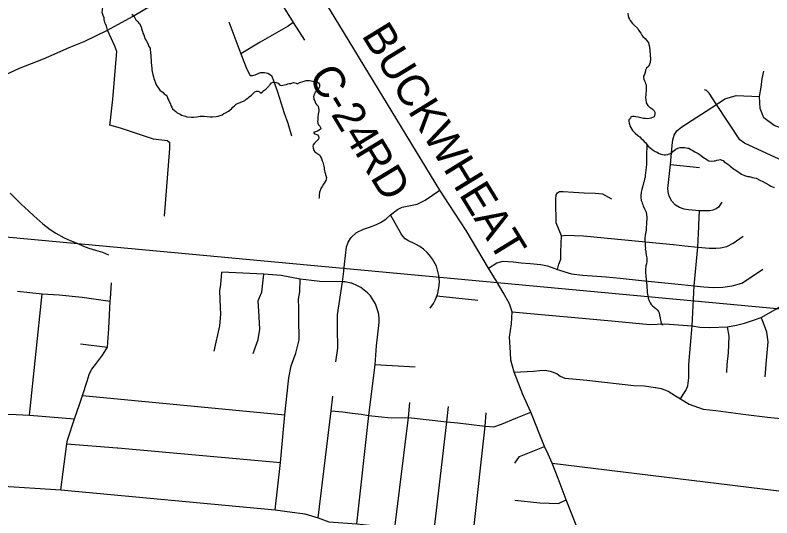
# Model space of a CAD drawing. Extents: x 0 to 34, y 0 to 22.
# Drawn here: x 7.879 to 8.564, y 19.556 to 20.011 of the extents above; entities that cross this region are included whole.
import ezdxf

# ---------------------------------------------------------------- set-up
doc = ezdxf.new("R2010")
doc.units = 0
for name, color, linetype in [('GM_X_County_Road', 7, 'Continuous'), ('GM_X_County_Road_Text', 7, 'Continuous'), ('GM_X_Minor_River', 7, 'Continuous'), ('GM_X_Rail_Line', 7, 'Continuous'), ('GM_X_State_Route', 7, 'Continuous'), ('GM_X_Township_Road', 7, 'Continuous')]:
    doc.layers.add(name, color=color, linetype=linetype)

msp = doc.modelspace()

# ---------------------------------------------------------------- linework, layer by layer
at = {"layer": 'GM_X_County_Road'}
msp.add_lwpolyline([(8.39269, 19.53489), (8.37799, 19.57233), (8.37085, 19.59153), (8.36519, 19.60541), (8.36182, 19.61363), (8.35845, 19.62064), (8.34603, 19.65165), (8.33882, 19.66764), (8.33096, 19.68798), (8.32794, 19.69886), (8.32754, 19.70571), (8.3267, 19.71954), (8.32834, 19.73169), (8.32893, 19.7424), (8.32665, 19.74986), (8.32103, 19.7599), (8.3148, 19.77035), (8.30767, 19.78207), (8.28725, 19.81622), (8.27202, 19.8398), (8.26366, 19.85264), (8.11273, 20.10048)], dxfattribs=at)
at = {"layer": 'GM_X_Minor_River'}
for points in [[(7.98432, 20.01186), (7.98618, 20.01049), (7.98727, 20.00856), (7.98818, 20.00702), (7.98929, 20.00567), (7.99151, 20.00333), (7.99277, 20.00065), (7.99311, 19.99893), (7.99418, 19.99625), (7.99452, 19.99472), (7.99524, 19.99319), (7.99595, 19.99108), (7.9963, 19.98993), (7.99775, 19.98743), (7.99884, 19.98532), (7.99972, 19.98264), (8.00102, 19.98128), (8.00116, 19.97957), (8.00149, 19.97766), (8.00179, 19.97424), (8.00174, 19.97254), (8.00189, 19.97083), (8.00201, 19.96798), (8.00215, 19.96589), (8.00245, 19.96266), (8.00261, 19.96152), (8.00295, 19.96018), (8.00345, 19.95732), (8.00397, 19.95541), (8.0045, 19.95369), (8.00484, 19.95236), (8.00592, 19.94986), (8.00644, 19.94795), (8.00865, 19.94505), (8.00974, 19.94313), (8.01291, 19.94096), (8.01383, 19.9398), (8.01551, 19.93862), (8.01643, 19.93745), (8.01714, 19.93535), (8.01786, 19.93381), (8.01949, 19.93055), (8.01983, 19.92921), (8.02074, 19.92767), (8.02128, 19.92633), (8.02426, 19.92398), (8.02537, 19.92281), (8.02837, 19.9214), (8.02949, 19.92062), (8.03307, 19.91958), (8.03439, 19.91916), (8.03837, 19.91887), (8.04027, 19.91863), (8.04331, 19.91893), (8.04637, 19.91961), (8.04751, 19.91977), (8.04998, 19.9197), (8.05281, 19.91925), (8.05528, 19.919), (8.05755, 19.91894), (8.06098, 19.91923), (8.0627, 19.91975), (8.06461, 19.92027), (8.06615, 19.92099), (8.06789, 19.92208), (8.06923, 19.92261), (8.07212, 19.92424), (8.07465, 19.92645), (8.07601, 19.92793), (8.07737, 19.92904), (8.07893, 19.93051), (8.08008, 19.93124), (8.08162, 19.93177), (8.08565, 19.93337), (8.0868, 19.93391), (8.08816, 19.9352), (8.0897, 19.93611), (8.09087, 19.93722), (8.09281, 19.93868), (8.09456, 19.94053), (8.09593, 19.94182), (8.09746, 19.94235), (8.09898, 19.94231)], [(8.43387, 20.01302), (8.43418, 20.01036), (8.43453, 20.00902), (8.43544, 20.00748), (8.43597, 20.00614), (8.43819, 20.00362), (8.43929, 20.00226)], [(8.43929, 20.00226), (8.44282, 19.99895), (8.44354, 19.9976), (8.44575, 19.9947), (8.44665, 19.99297), (8.44757, 19.99181), (8.44943, 19.99005), (8.45072, 19.9885), (8.45183, 19.98734), (8.45275, 19.98598), (8.4529, 19.98465), (8.45325, 19.98351), (8.45373, 19.9797), (8.45388, 19.97837), (8.45401, 19.9759), (8.45397, 19.97438), (8.45428, 19.97172), (8.4542, 19.96831), (8.45359, 19.96681), (8.45278, 19.96493), (8.45065, 19.96309), (8.44984, 19.96141), (8.4496, 19.95933), (8.44898, 19.95745), (8.44819, 19.95595), (8.44796, 19.95463), (8.44831, 19.95329), (8.44884, 19.95157), (8.44957, 19.95042), (8.44992, 19.94927), (8.45046, 19.94812), (8.45059, 19.94584), (8.4505, 19.94243), (8.45027, 19.94054), (8.45004, 19.93922), (8.44997, 19.93619), (8.45012, 19.93466), (8.45043, 19.93181), (8.45207, 19.92931), (8.45355, 19.92775), (8.45468, 19.92715), (8.45636, 19.92597), (8.45765, 19.92442), (8.45819, 19.92327), (8.45834, 19.92175), (8.4577, 19.91911), (8.45482, 19.91786), (8.45348, 19.91751), (8.45196, 19.91736), (8.44987, 19.91742), (8.44798, 19.91765), (8.44571, 19.91809), (8.44326, 19.91873), (8.44118, 19.91897), (8.43948, 19.91939), (8.43796, 19.91943), (8.43662, 19.91909), (8.43621, 19.91796), (8.43484, 19.91629), (8.43481, 19.91515), (8.43515, 19.91344), (8.43602, 19.91019), (8.43801, 19.90654), (8.44042, 19.9042), (8.44284, 19.90224), (8.44471, 19.90086), (8.446, 19.8995), (8.44749, 19.89814), (8.44859, 19.89678), (8.45008, 19.89541), (8.45099, 19.89406), (8.45228, 19.89251), (8.45377, 19.89115), (8.456, 19.88938), (8.45862, 19.8878), (8.46031, 19.88699), (8.46162, 19.8862), (8.46388, 19.88538), (8.4667, 19.88455), (8.46803, 19.88452), (8.46975, 19.88485), (8.47358, 19.88627), (8.47476, 19.88757), (8.47728, 19.88977), (8.4792, 19.89067), (8.48131, 19.89119), (8.48397, 19.89131), (8.4853, 19.89127), (8.48681, 19.89104), (8.48813, 19.89082), (8.48927, 19.8906), (8.49039, 19.88981), (8.49207, 19.88882), (8.4945, 19.88724), (8.4975, 19.88583), (8.49937, 19.88465), (8.50124, 19.88327), (8.50328, 19.88151), (8.50459, 19.88091), (8.5059, 19.88011), (8.5074, 19.87932)], [(8.09898, 19.94231), (8.1001, 19.94172), (8.10121, 19.94055), (8.10276, 19.94184), (8.10411, 19.94275), (8.10586, 19.94422), (8.10742, 19.9457), (8.11015, 19.94866), (8.11113, 19.94977), (8.11247, 19.95031), (8.11532, 19.95023), (8.11701, 19.94962), (8.1183, 19.94807), (8.12019, 19.94745), (8.12286, 19.94814), (8.12458, 19.94847), (8.12592, 19.94882), (8.12707, 19.94916), (8.1284, 19.94932), (8.12955, 19.94967), (8.13088, 19.95001), (8.13202, 19.94998), (8.13334, 19.94957), (8.13466, 19.94897), (8.13678, 19.95024), (8.13983, 19.95092), (8.14252, 19.95199), (8.14556, 19.95191), (8.14688, 19.95168), (8.1482, 19.95127), (8.15028, 19.95102), (8.15255, 19.95059), (8.15367, 19.94999), (8.1544, 19.94864), (8.15437, 19.9475), (8.15453, 19.94636), (8.15393, 19.94505), (8.15333, 19.94393), (8.15196, 19.94226), (8.1506, 19.94116), (8.14981, 19.93985), (8.14921, 19.93854), (8.14917, 19.93702), (8.14933, 19.93588), (8.14949, 19.93474), (8.15022, 19.93358), (8.15092, 19.93129), (8.15165, 19.93013), (8.15313, 19.92857), (8.15366, 19.92704), (8.15382, 19.9259), (8.15379, 19.92458), (8.15334, 19.92156), (8.15289, 19.91891), (8.15286, 19.91759), (8.15282, 19.91626), (8.15279, 19.91493), (8.15294, 19.91341), (8.15366, 19.91188), (8.15477, 19.91052), (8.15531, 19.90937), (8.15566, 19.90822), (8.15411, 19.90693), (8.15256, 19.90603), (8.14912, 19.90498), (8.14984, 19.90363), (8.15117, 19.90341), (8.15267, 19.9028), (8.15359, 19.90145), (8.15393, 19.89992), (8.15352, 19.8988), (8.15235, 19.8975), (8.15099, 19.89621), (8.15001, 19.8951), (8.14864, 19.89361), (8.14842, 19.89248), (8.14876, 19.89077), (8.14946, 19.88847), (8.15019, 19.88732), (8.15468, 19.88436), (8.1554, 19.88282), (8.15631, 19.88128), (8.15701, 19.87918), (8.15756, 19.87802), (8.15791, 19.87688), (8.15806, 19.87554), (8.15841, 19.8744), (8.15856, 19.87288), (8.15873, 19.87174), (8.15907, 19.87021), (8.15923, 19.86907), (8.15958, 19.86792), (8.16028, 19.86582), (8.16081, 19.8641), (8.16058, 19.86259), (8.16017, 19.86127), (8.15918, 19.85978), (8.15819, 19.8581), (8.157, 19.85604), (8.15621, 19.85493), (8.15541, 19.85343)], [(8.45099, 19.89406), (8.45092, 19.88383), (8.45065, 19.88061), (8.45078, 19.87833), (8.45073, 19.87625), (8.45047, 19.87322), (8.44997, 19.86849), (8.44973, 19.8666), (8.44948, 19.86414), (8.44906, 19.86283), (8.44862, 19.86037), (8.44802, 19.85925), (8.44739, 19.85661), (8.44654, 19.85322), (8.4461, 19.85077), (8.44564, 19.84756), (8.44561, 19.84642), (8.4461, 19.84337), (8.44645, 19.84223), (8.4468, 19.84089), (8.44734, 19.83974), (8.44769, 19.83859), (8.44895, 19.83572), (8.45039, 19.83283), (8.45091, 19.83054), (8.45103, 19.82789), (8.45119, 19.82675), (8.45092, 19.82334), (8.45089, 19.8222), (8.4506, 19.81842), (8.45036, 19.81653), (8.44968, 19.81199), (8.44941, 19.80878), (8.44938, 19.80764), (8.44949, 19.80461), (8.44961, 19.80176), (8.44976, 19.80024), (8.44973, 19.79891), (8.45008, 19.79776), (8.45024, 19.79662), (8.45055, 19.79377), (8.45106, 19.79129), (8.45098, 19.78845), (8.45073, 19.78599), (8.45012, 19.78411), (8.44985, 19.78127), (8.4498, 19.77919), (8.44995, 19.77767), (8.45008, 19.77539), (8.45056, 19.77159), (8.45086, 19.76854), (8.45101, 19.76683), (8.45096, 19.76475), (8.45125, 19.76152), (8.45141, 19.76), (8.4519, 19.75714), (8.45241, 19.75485), (8.45312, 19.75256), (8.45421, 19.75063), (8.45512, 19.74928), (8.45623, 19.74792), (8.45772, 19.74675), (8.45939, 19.74538), (8.4605, 19.74421), (8.46161, 19.74285), (8.46214, 19.74151), (8.46247, 19.73942), (8.46316, 19.73675), (8.4635, 19.73503), (8.46366, 19.73389), (8.46419, 19.73217), (8.46511, 19.73101), (8.46534, 19.73051)], [(8.5074, 19.87932), (8.51006, 19.87906), (8.51196, 19.8792), (8.5131, 19.87917), (8.51463, 19.8797), (8.51635, 19.88022), (8.51788, 19.88056), (8.51919, 19.87996), (8.52032, 19.87955), (8.52124, 19.87839), (8.52274, 19.8774), (8.52554, 19.87562), (8.52665, 19.87426), (8.53038, 19.87151), (8.53169, 19.87091), (8.53373, 19.86915), (8.53486, 19.86855), (8.53691, 19.86717), (8.53954, 19.86596), (8.54275, 19.86512), (8.54388, 19.8649), (8.54671, 19.86426), (8.54841, 19.86384), (8.5503, 19.86341), (8.55405, 19.86141), (8.55574, 19.8608), (8.56155, 19.85761), (8.56342, 19.85643), (8.56642, 19.85502)], [(8.15541, 19.85343), (8.15501, 19.8523), (8.15459, 19.8508), (8.15414, 19.84815), (8.1541, 19.84645), (8.15388, 19.84513)], [(7.8742, 19.8498), (7.87922, 19.84496), (7.88424, 19.83994), (7.89075, 19.83393), (7.89558, 19.82929), (7.90377, 19.82231), (7.9103, 19.81706), (7.91554, 19.81374), (7.92303, 19.80961), (7.92848, 19.80723), (7.93543, 19.80444), (7.9405, 19.80188), (7.94558, 19.80008), (7.95142, 19.79845), (7.95782, 19.79643), (7.96327, 19.79405)]]:
    msp.add_lwpolyline(points, dxfattribs=at)
at = {"layer": 'GM_X_Rail_Line'}
msp.add_lwpolyline([(8.9, 19.7176), (8.69584, 19.73341), (7.47033, 19.84735), (7.26736, 19.78133), (7.23591, 19.76162), (7.19492, 19.71716), (7.16666, 19.69799), (6.88858, 19.5517)], dxfattribs=at)
at = {"layer": 'GM_X_State_Route'}
for points in [[(7.91682, 19.97713), (7.92004, 19.97854), (7.92773, 19.98177), (7.94137, 19.98719), (7.96248, 19.99744), (7.98495, 20.00979), (8.00288, 20.02054), (8.02211, 20.03292), (8.02788, 20.037)], [(7.86146, 19.95391), (7.87358, 19.95904), (7.88275, 19.96311), (7.9044, 19.97168), (7.91682, 19.97713)]]:
    msp.add_lwpolyline(points, dxfattribs=at)
at = {"layer": 'GM_X_Township_Road'}
for p, q in [((8.47244, 19.87583), (8.49873, 19.87312)), ((7.89162, 19.64894), (7.90311, 19.75889)), ((8.26089, 19.75699), (8.2979, 19.75322)), ((7.93796, 19.7136), (7.96235, 19.71058)), ((8.20488, 19.69492), (8.2413, 19.69259)), ((7.93962, 19.66682), (8.12302, 19.64915)), ((7.97168, 19.61925), (8.11927, 19.60609)), ((8.36519, 19.60541), (8.64163, 19.57175))]:
    msp.add_line(p, q, dxfattribs=at)
for points in [[(8.08448, 20.07912), (8.13072, 20.00445), (8.14074, 19.98843)], [(8.01402, 19.82919), (8.01878, 19.89032), (8.01873, 19.89566), (8.01656, 19.89739), (8.0041, 19.8987), (7.9742, 19.90874), (7.96457, 19.9114), (7.96498, 19.91591), (7.96723, 19.93496), (7.97078, 19.97816), (7.96906, 19.98303), (7.96248, 19.99744), (7.96134, 20.00111), (7.9605, 20.00312), (7.96007, 20.00449), (7.95933, 20.00713), (7.95923, 20.00883), (7.95859, 20.01073), (7.95743, 20.01337), (7.9586, 20.02072), (7.95793, 20.03073), (7.95571, 20.03852), (7.95303, 20.04743), (7.99133, 20.05876)], [(8.07244, 20.005), (8.08319, 19.97622), (8.08872, 19.96213)], [(8.13072, 20.00445), (8.12617, 20.00118), (8.10085, 19.98679), (8.08319, 19.97622)], [(8.08872, 19.96213), (8.0889, 19.96166), (8.09162, 19.95658), (8.09384, 19.95643), (8.09613, 19.95715), (8.10113, 19.95908), (8.10464, 19.95922), (8.10765, 19.95851), (8.11108, 19.95651), (8.11308, 19.95107), (8.1163, 19.94184), (8.1226, 19.92252), (8.12582, 19.91336), (8.12918, 19.90192)], [(8.57865, 19.90654), (8.56647, 19.91135), (8.55711, 19.91821), (8.55368, 19.92664), (8.55311, 19.93742), (8.55477, 19.94583), (8.5557, 19.95348), (8.55711, 19.9605)], [(8.6063, 19.76663), (8.60397, 19.77939), (8.59843, 19.79347), (8.57389, 19.83083), (8.58535, 19.83769), (8.59331, 19.84378), (8.59643, 19.84971), (8.59768, 19.85501), (8.59674, 19.86125), (8.59474, 19.86498), (8.59013, 19.87144), (8.58228, 19.87605), (8.56774, 19.88229), (8.53953, 19.89515), (8.53525, 19.89831), (8.51411, 19.93013), (8.5075, 19.94054), (8.50516, 19.94289), (8.50332, 19.9436)], [(8.51891, 19.84186), (8.51593, 19.8372), (8.5138, 19.83582), (8.51091, 19.83455), (8.50818, 19.83388), (8.50504, 19.83388), (8.49892, 19.83392), (8.48881, 19.83489), (8.48482, 19.83535), (8.48064, 19.83684), (8.47713, 19.83916), (8.47367, 19.84272), (8.47124, 19.84726), (8.47032, 19.85108), (8.47021, 19.85415), (8.47244, 19.87583), (8.47405, 19.89301), (8.47466, 19.89831), (8.47588, 19.90239), (8.47833, 19.90627), (8.48282, 19.91004), (8.51411, 19.93013), (8.52189, 19.93546), (8.53198, 19.9385), (8.55311, 19.93742)], [(8.1764, 19.77938), (8.17708, 19.78572), (8.17884, 19.80145), (8.18055, 19.80571), (8.18325, 19.80984), (8.18787, 19.81421), (8.19428, 19.81729), (8.19967, 19.81908), (8.20602, 19.82144), (8.20984, 19.82338), (8.21456, 19.82653), (8.21882, 19.83034), (8.22509, 19.83526), (8.22953, 19.83728), (8.23381, 19.83808), (8.24305, 19.83988), (8.25024, 19.84373), (8.26366, 19.85264)], [(8.37027, 19.7809), (8.37146, 19.78581), (8.37313, 19.79024), (8.37319, 19.79687), (8.3737, 19.81136), (8.36893, 19.82315), (8.36854, 19.84276), (8.36855, 19.84428), (8.369, 19.84848), (8.3702, 19.85038), (8.37202, 19.8515), (8.37532, 19.85143), (8.38451, 19.85094), (8.39427, 19.85038), (8.40423, 19.84989), (8.41083, 19.84939), (8.41897, 19.84469)], [(8.49828, 19.81989), (8.49835, 19.82129), (8.49892, 19.83392)], [(8.25463, 19.74568), (8.25778, 19.75004), (8.25966, 19.75376), (8.26089, 19.75699), (8.26129, 19.75804), (8.26268, 19.76425), (8.26312, 19.76961), (8.26264, 19.77554), (8.26149, 19.78031), (8.2604, 19.78388), (8.257, 19.79009), (8.25423, 19.79378), (8.25192, 19.79634), (8.24861, 19.79927), (8.24536, 19.80155), (8.24157, 19.80365), (8.23465, 19.80704), (8.23201, 19.80875), (8.2299, 19.81094), (8.22839, 19.81311), (8.21882, 19.83034)], [(8.48172, 19.66386), (8.48405, 19.6678), (8.48628, 19.67124), (8.48835, 19.6755), (8.48912, 19.68272), (8.48927, 19.69491), (8.49211, 19.72991), (8.49396, 19.76599), (8.49732, 19.80113), (8.49828, 19.81989)], [(8.3737, 19.81136), (8.37742, 19.81204), (8.3938, 19.81121), (8.46566, 19.80451), (8.47534, 19.8036), (8.48543, 19.80236), (8.49732, 19.80113), (8.50082, 19.80079), (8.50768, 19.80029), (8.51356, 19.80013), (8.51794, 19.80038), (8.52365, 19.80162), (8.5292, 19.80468), (8.5383, 19.81105)], [(8.30767, 19.78207), (8.31532, 19.78687), (8.321, 19.78841), (8.32991, 19.78778), (8.33735, 19.78678), (8.34548, 19.78613), (8.3549, 19.78525), (8.36114, 19.78406), (8.37027, 19.7809), (8.37672, 19.77873), (8.38297, 19.77704), (8.39294, 19.77571), (8.40585, 19.77472), (8.41427, 19.77423), (8.42704, 19.77311), (8.44627, 19.77079), (8.48249, 19.76729), (8.49396, 19.76599), (8.50274, 19.76521), (8.51132, 19.76449), (8.52001, 19.7649), (8.52829, 19.76604), (8.53719, 19.76853), (8.54516, 19.77349), (8.55612, 19.78115)], [(8.05898, 19.70691), (8.06425, 19.72975), (8.06513, 19.74041), (8.06469, 19.74655), (8.06451, 19.75408), (8.06403, 19.76149), (8.06513, 19.7672), (8.06603, 19.77833)], [(8.18824, 19.55047), (8.19929, 19.64862), (8.20488, 19.69492), (8.20604, 19.71162), (8.20845, 19.73288), (8.20861, 19.73631), (8.20815, 19.74001), (8.20744, 19.74327), (8.20513, 19.74978), (8.20056, 19.75694), (8.19793, 19.75983), (8.19198, 19.76448), (8.18891, 19.76618), (8.18366, 19.76837), (8.18286, 19.76854), (8.17774, 19.76964), (8.17536, 19.76962), (8.15468, 19.77004), (8.14727, 19.77088), (8.13682, 19.77207), (8.11971, 19.77533), (8.10401, 19.77654), (8.06603, 19.77833)], [(8.09434, 19.70471), (8.09885, 19.71734), (8.10049, 19.7269), (8.09994, 19.73799), (8.09907, 19.74798), (8.09885, 19.75249), (8.10005, 19.75545), (8.10214, 19.76028), (8.10401, 19.77654)], [(8.16939, 19.69729), (8.17105, 19.70974), (8.17093, 19.72771), (8.1708, 19.73977), (8.17536, 19.76962), (8.1764, 19.77938)], [(7.93962, 19.66682), (7.94389, 19.67968), (7.94585, 19.68591), (7.94701, 19.68836), (7.94816, 19.69063), (7.95161, 19.69476), (7.95793, 19.70323), (7.96235, 19.71058), (7.96351, 19.72753), (7.96476, 19.75222), (7.96506, 19.75469), (7.96612, 19.7688)], [(8.12649, 19.68007), (8.12678, 19.68265), (8.12872, 19.69373), (8.13289, 19.70494), (8.13597, 19.71701), (8.13575, 19.73678), (8.13575, 19.74601), (8.13552, 19.75391), (8.13662, 19.7605), (8.13682, 19.77207)], [(7.88082, 19.76122), (7.90311, 19.75889), (7.91868, 19.75796), (7.93935, 19.75587), (7.96476, 19.75222)], [(8.46726, 19.73178), (8.49211, 19.72991), (8.4992, 19.72856), (8.50817, 19.72846), (8.5242, 19.72907), (8.53219, 19.73034), (8.53972, 19.73228), (8.54582, 19.73436), (8.55468, 19.73741), (8.56801, 19.745), (8.57767, 19.7511), (8.58296, 19.75466), (8.59338, 19.76156)], [(8.32893, 19.7424), (8.42227, 19.73399), (8.45381, 19.73097), (8.46726, 19.73178)], [(8.55844, 19.68366), (8.55967, 19.69874), (8.56104, 19.71532), (8.55992, 19.72422), (8.55646, 19.73313), (8.55468, 19.73741)], [(8.52344, 19.68761), (8.52393, 19.69486), (8.52499, 19.70545), (8.52539, 19.71283), (8.52579, 19.72063), (8.5242, 19.72907)], [(8.33096, 19.68798), (8.34828, 19.68879), (8.35406, 19.68949), (8.3589, 19.68967), (8.36348, 19.6889), (8.3662, 19.68797), (8.36976, 19.68627), (8.37265, 19.68423), (8.37689, 19.68245), (8.38708, 19.68143), (8.39658, 19.68067), (8.43928, 19.67583), (8.44887, 19.67549), (8.45871, 19.67413), (8.45919, 19.67404)], [(8.11442, 19.56312), (8.11927, 19.60609), (8.12302, 19.64915), (8.12649, 19.68007)], [(8.45919, 19.67404), (8.46398, 19.67311), (8.47051, 19.67057), (8.47714, 19.66658), (8.48172, 19.66386), (8.48944, 19.65885), (8.502, 19.65427), (8.51355, 19.65308), (8.54088, 19.6496), (8.56048, 19.64714), (8.58467, 19.64459), (8.59375, 19.64366), (8.60326, 19.64273), (8.61411, 19.6439), (8.62694, 19.64952), (8.63882, 19.6575)], [(7.91999, 19.58144), (7.9221, 19.59765), (7.9256, 19.62298), (7.92616, 19.62641), (7.93255, 19.64561), (7.93689, 19.65865), (7.93962, 19.66682)], [(8.15339, 19.55612), (8.16494, 19.6528), (8.16656, 19.66617)], [(8.22285, 19.54686), (8.23508, 19.64671), (8.23629, 19.66043)], [(8.16494, 19.6528), (8.17561, 19.65185), (8.18399, 19.6509), (8.19224, 19.64996), (8.19929, 19.64862), (8.20751, 19.64766), (8.2194, 19.64658), (8.23508, 19.64671), (8.26981, 19.64307), (8.27995, 19.64198), (8.28968, 19.6409), (8.30448, 19.63894), (8.31252, 19.63847), (8.31934, 19.64077), (8.33245, 19.64611), (8.34603, 19.65165)], [(8.25834, 19.54439), (8.26981, 19.64307), (8.27123, 19.65692)], [(7.86816, 19.65001), (7.8795, 19.64966), (7.89162, 19.64894), (7.93255, 19.64561)], [(8.28843, 19.51621), (8.2916, 19.52361), (8.29295, 19.53088), (8.29363, 19.54099), (8.30448, 19.63894), (8.30556, 19.65094)], [(7.9256, 19.62298), (7.97117, 19.6193), (7.97168, 19.61925)], [(8.33163, 19.60541), (8.33567, 19.61161), (8.35845, 19.62064)], [(7.86331, 19.58497), (7.91999, 19.58144), (8.11442, 19.56312), (8.1297, 19.56111), (8.1392, 19.55986)], [(8.33136, 19.57185), (8.35427, 19.5697), (8.37098, 19.56902), (8.37799, 19.57233)], [(8.1392, 19.55986), (8.1412, 19.5596), (8.15339, 19.55612), (8.16291, 19.55252), (8.18824, 19.55047), (8.22285, 19.54686), (8.25834, 19.54439), (8.28925, 19.54143), (8.29363, 19.54099), (8.38402, 19.53276), (8.39269, 19.53489)]]:
    msp.add_lwpolyline(points, dxfattribs=at)

# ---------------------------------------------------------------- texts
at = {"layer": 'GM_X_County_Road_Text'}
for s, rotation, p in [('BUCKWHEAT', 301.53032, (8.19214, 19.99282)), ('C-24', 301.31512, (8.1437, 19.95559)), ('RD', 301.21924, (8.18577, 19.8876))]:
    msp.add_text(s, height=0.028409, rotation=rotation, dxfattribs=at).set_placement(p)

doc.saveas('drawing.dxf')
